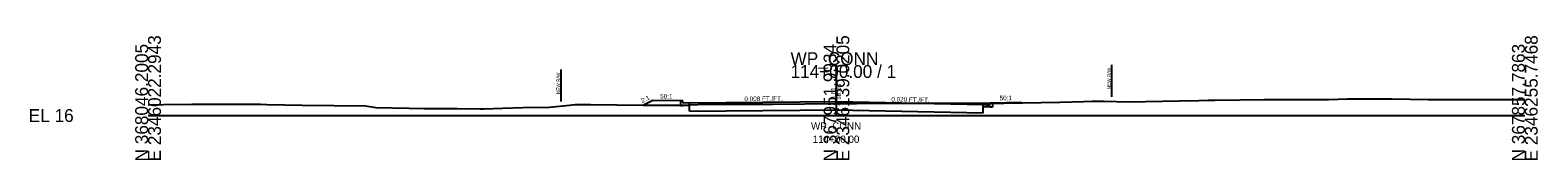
# Model space of a CAD drawing. Extents: x -26 to 2345577, y -10 to 367097.
# Drawn here: x 974.3 to 1302.8, y 3990.3 to 4017.3 of the extents above; entities that cross this region are included whole.
import ezdxf

# ---------------------------------------------------------------- set-up
doc = ezdxf.new("R2010")
doc.units = 0
for name, color, linetype in [('RD_GPK_XS_Cell', 7, 'Continuous'), ('RD_XS_Base', 7, 'Continuous'), ('RD_XS_CurbTop', 7, 'Continuous'), ('RD_XS_EarthShd', 7, 'Continuous'), ('RD_XS_ExGround', 7, 'Continuous'), ('RD_XS_NewRW', 7, 'Continuous'), ('RD_XS_Pave', 7, 'Continuous'), ('RD_XS_TieSlope', 7, 'Continuous'), ('RD_XS_TX_Elev_EX', 7, 'Continuous'), ('RD_XS_TX_Elev_PR', 7, 'Continuous'), ('RD_XS_TX_Slope', 7, 'Continuous'), ('RD_XS_TX_Station', 7, 'Continuous'), ('RD_XS_TX_TOC', 7, 'Continuous')]:
    doc.layers.add(name, color=color, linetype=linetype)

msp = doc.modelspace()

# ---------------------------------------------------------------- linework, layer by layer
at = {"layer": 'RD_GPK_XS_Cell'}
for p, q in [((1150, 4000), (1150, 4010.99)), ((1000, 4000), (1150, 4000)), ((1150, 4000), (1300, 4000))]:
    msp.add_line(p, q, dxfattribs=at)
at = {"layer": 'RD_XS_Base'}
for p, q in [((1116, 4003.18), (1116, 4002.18)), ((1116, 4002.18), (1116.5, 4002.18)), ((1116.5, 4002.18), (1118, 4002.26)), ((1118, 4002.26), (1118, 4002.76)), ((1118, 4000.98), (1118, 4002.26)), ((1182, 4001.87), (1182, 4002.37)), ((1183.5, 4001.79), (1182, 4001.87)), ((1182, 4000.59), (1182, 4001.87)), ((1184, 4001.79), (1183.5, 4001.79)), ((1184, 4002.79), (1184, 4001.79)), ((1118, 4000.98), (1149.99, 4001.23)), ((1149.99, 4001.23), (1182, 4000.59))]:
    msp.add_line(p, q, dxfattribs=at)
at = {"layer": 'RD_XS_CurbTop'}
for p, q in [((1116.5, 4003.18), (1116, 4003.18)), ((1116.58, 4002.68), (1116.5, 4003.18)), ((1118, 4002.76), (1116.58, 4002.68)), ((1118, 4002.78), (1118, 4002.76)), ((1182, 4002.39), (1182, 4002.37)), ((1182, 4002.37), (1183.42, 4002.29)), ((1183.42, 4002.29), (1183.5, 4002.79)), ((1183.5, 4002.79), (1184, 4002.79))]:
    msp.add_line(p, q, dxfattribs=at)
at = {"layer": 'RD_XS_EarthShd'}
for p, q in [((1116, 4003.18), (1110, 4003.3)), ((1184, 4002.79), (1190, 4002.91))]:
    msp.add_line(p, q, dxfattribs=at)
at = {"layer": 'RD_XS_ExGround'}
msp.add_lwpolyline([(1000, 4002.33), (1003.34, 4002.38), (1009.51, 4002.47), (1009.89, 4002.47), (1010.84, 4002.47), (1022.92, 4002.45), (1024.48, 4002.47), (1025.9, 4002.43), (1033.61, 4002.26), (1047.4, 4002.08), (1049.65, 4001.77), (1056.92, 4001.61), (1060.14, 4001.55), (1066.03, 4001.51), (1067.36, 4001.5), (1072.38, 4001.48), (1072.68, 4001.48), (1073.23, 4001.48), (1077.22, 4001.59), (1081.67, 4001.78), (1087.48, 4001.79), (1091.85, 4002.24), (1093.11, 4002.43), (1096.39, 4002.38), (1107.89, 4002.27), (1116.33, 4002.25), (1117.7, 4002.33), (1121.95, 4002.46), (1128.46, 4002.48), (1130.82, 4002.49), (1136.17, 4002.5), (1150, 4002.61), (1152.86, 4002.64), (1154.38, 4002.65), (1155.45, 4002.66), (1162.96, 4002.72), (1173.25, 4002.7), (1176.19, 4002.7), (1182.15, 4002.67), (1186.47, 4002.72), (1198.67, 4002.91), (1203.84, 4003.08), (1205.68, 4003.12), (1208.34, 4003.12), (1213.67, 4003), (1224.75, 4003.19), (1228.95, 4003.28), (1230.92, 4003.31), (1232.47, 4003.34), (1243.27, 4003.46), (1247.44, 4003.5), (1248.4, 4003.52), (1249.46, 4003.5), (1257.29, 4003.51), (1261.33, 4003.64), (1264.3, 4003.66), (1266.64, 4003.64), (1271.1, 4003.6), (1278.91, 4003.51), (1280.88, 4003.51), (1282.31, 4003.5), (1286.89, 4003.5), (1291.75, 4003.5), (1295.31, 4003.5), (1300, 4003.5)], dxfattribs=at)
at = {"layer": 'RD_XS_NewRW'}
for p, q in [((1090, 4003.05), (1090, 4010.05)), ((1210, 4004.08), (1210, 4011.08))]:
    msp.add_line(p, q, dxfattribs=at)
at = {"layer": 'RD_XS_Pave'}
for p, q in [((1118, 4002.78), (1150, 4003.03)), ((1150, 4003.03), (1182, 4002.39))]:
    msp.add_line(p, q, dxfattribs=at)
at = {"layer": 'RD_XS_TieSlope'}
for p, q in [((1110, 4003.3), (1107.95, 4002.27)), ((1190, 4002.91), (1190.26, 4002.78))]:
    msp.add_line(p, q, dxfattribs=at)

# ---------------------------------------------------------------- texts
at = {"layer": 'RD_GPK_XS_Cell'}
for s, p in [('N 368046.2005', (1000, 3990)), ('E 2346022.2943', (1002.8, 3990)), ('N 367951.9934', (1150, 3990)), ('E 2346139.0205', (1152.8, 3990)), ('N 367857.7863', (1300, 3990)), ('E 2346255.7468', (1302.8, 3990))]:
    msp.add_text(s, height=2.8, rotation=90, dxfattribs=at).set_placement(p)
for s, p in [('WP_CONN', (1140, 4010.99)), ('114+00.00 / 1', (1140, 4008.19)), ('EL 16', (974, 3998.6))]:
    msp.add_text(s, height=2.8, dxfattribs=at).set_placement(p)
at = {"layer": 'RD_XS_NewRW'}
for p in [(1089.75, 4004.63), (1209.75, 4005.67)]:
    msp.add_text('NEW R/W ', height=0.75, rotation=90, dxfattribs=at).set_placement(p)
at = {"layer": 'RD_XS_TX_Elev_EX'}
msp.add_text('18.61', height=1, rotation=90, dxfattribs=at).set_placement((1149.82, 4002.66))
at = {"layer": 'RD_XS_TX_Elev_PR'}
for s, rotation, p in [(' 19.03', 90, (1151, 4003.03)), ('2:1', 26.5651, (1107.71, 4002.72)), ('50:1', 358.8542, (1111.58, 4003.71)), ('50:1', 1.1458, (1185.57, 4003.3))]:
    msp.add_text(s, height=1, rotation=rotation, dxfattribs=at).set_placement(p)
at = {"layer": 'RD_XS_TX_Slope'}
for s, rotation, p in [('0.008 FT./FT.', 0.4437, (1129.95, 4003.13)), ('0.020 FT./FT.', 358.8542, (1161.95, 4003.04))]:
    msp.add_text(s, height=1, rotation=rotation, dxfattribs=at).set_placement(p)
at = {"layer": 'RD_XS_TX_Station'}
for s, p in [('WP_CONN', (1144.45, 3996.93)), ('114+00.00', (1144.83, 3994.03))]:
    msp.add_text(s, height=1.6, dxfattribs=at).set_placement(p)
at = {"layer": 'RD_XS_TX_TOC'}
for s, p in [('TOCLT', (1116.55, 4003.13)), ('TOCRT', (1183.22, 4002.74))]:
    msp.add_text(s, height=0.05, dxfattribs=at).set_placement(p)

doc.saveas('drawing.dxf')
